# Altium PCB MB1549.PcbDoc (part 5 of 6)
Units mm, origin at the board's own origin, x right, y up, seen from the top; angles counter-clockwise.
Board outline 70 x 133.34 mm, 6 copper layers (Top Layer, Signal Layer 1, Signal Layer 2, Signal Layer 3, Signal Layer 4, Bottom Layer), stack 1.57 mm thick; 289 components, 250 nets, 1288 pads, 875 vias.
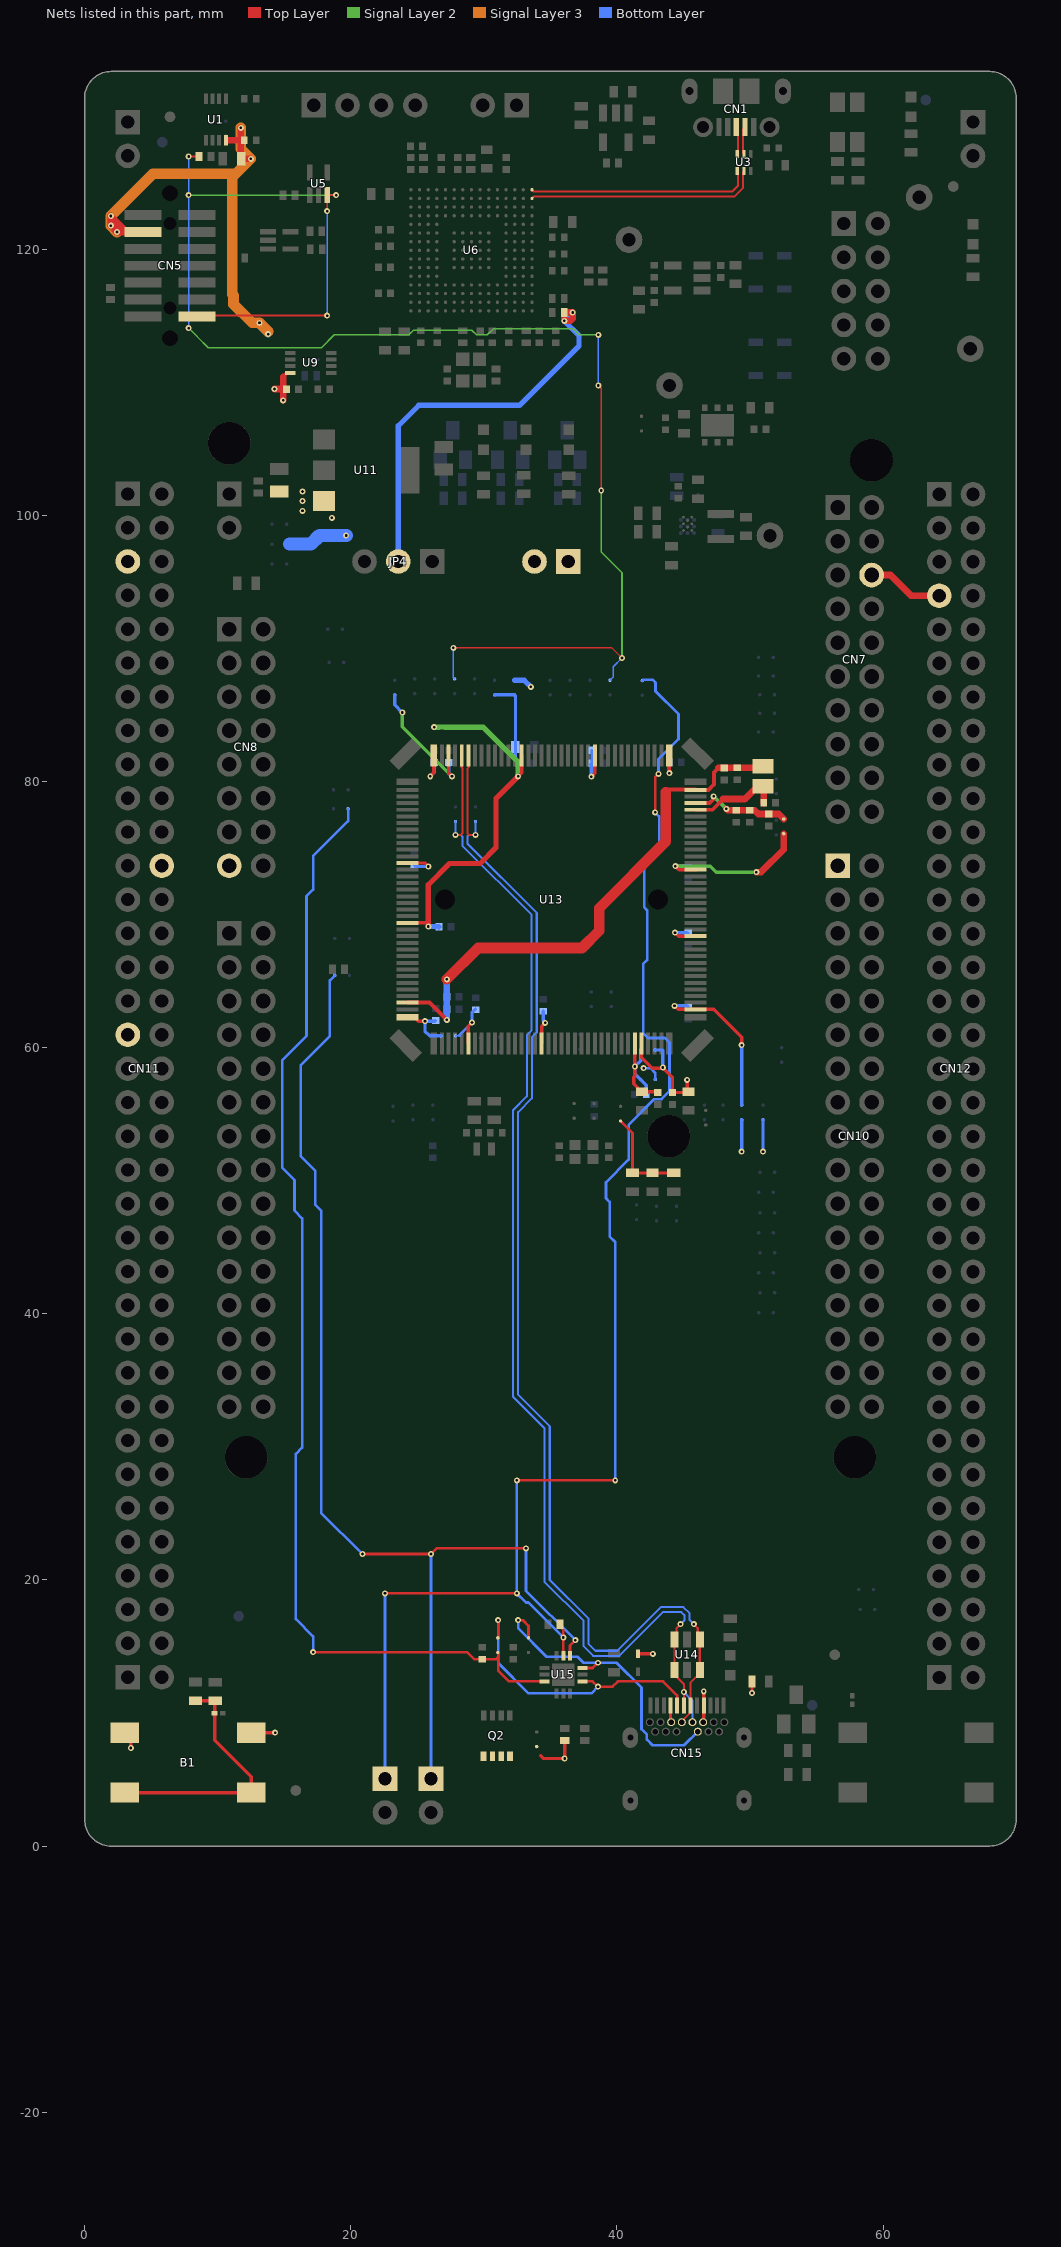
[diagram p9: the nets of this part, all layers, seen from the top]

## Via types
v1: diameter 0.45, hole 0.2, Top Layer to Bottom Layer, tented both sides, 875 vias

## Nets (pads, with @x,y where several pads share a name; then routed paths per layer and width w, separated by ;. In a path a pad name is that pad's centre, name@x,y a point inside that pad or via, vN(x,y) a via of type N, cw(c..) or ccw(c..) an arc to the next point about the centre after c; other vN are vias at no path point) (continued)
T_VCP_TX: CN5.14 R3.1 SB24.1 SB32.2 U5.3 | length 119.3
  Top Layer w0.12: v1(7.816,126.954) R3.1@8.591,126.954 ; CN5.14@8.341,114.812 CN5.14@8.458,114.929 ; CN5.14@8.453,114.934 9.516,114.934 9.587,115.005 18.22,115.005 v1(18.225,115) ; v1(18.225,122.849) U5.3@18.225,124.05 v1(18.9,124.05) ; v1(27.706,90.031) 39.62,90.031 v1(40.376,89.275) ; v1(38.6,109.75) 38.818,109.532 v1(38.818,101.857)
  Signal Layer 2 w0.12: v1(7.816,114.059) 8.475,113.4 8.475,113.395 9.28,112.59 17.796,112.59 18.765,113.559 24.365,113.559 24.71,113.904 29.097,113.904 29.442,113.559 30.261,113.559 30.716,114.014 36.714,114.014 37.169,113.559 v1(38.6,113.559) ; v1(7.816,124.05) v1(18.9,124.05) ; v1(38.818,101.857) 38.818,97.231 40.376,95.672 v1(40.376,89.275)
  Bottom Layer w0.12: v1(7.816,114.059) v1(7.816,124.05) v1(7.816,126.954) ; v1(18.225,115) v1(18.225,122.849) ; v1(27.706,90.031) 27.706,87.794 SB32.2@27.8,87.7 ; v1(38.6,109.75) v1(38.6,113.559) ; SB24.1@39.475,87.6 39.725,87.85 39.725,88.624 v1(40.376,89.275)
UCPD_CC1: C62.2 SB8.1 SB42.1 U15.3 | length 86.2
  Top Layer w0.2: v1(17.17,14.581) 28.744,14.581 29.275,14.05 C62.2@29.875,14.05 30.92,14.05 31.07,14.2 ; SB8.1@31.05,14.581 31.07,14.581 31.07,14.55 31.07,14.2 ; U15.3@34.545,12.381 31.87,12.381 31.07,13.181 31.07,14.2
  Bottom Layer w0.2: v1(17.17,14.581) 17.17,15.762 15.875,17.057 15.875,29.475 16.35,29.95 16.35,47.175 15.77,47.755 15.77,50.05 14.84,50.98 14.84,59.04 16.67,60.87 16.67,71.381 17.17,71.881 17.17,74.395 19.8,77.025 SB42.1@19.8,77.95
UCPD_CC1_C: CN15.A5 SB8.2 U15.7 | length 21.8
  Top Layer w0.2: SB8.2@31.07,15.681 v1(31.07,16.981) ; U15.7@37.395,12.381 38.17,12.381 v1(38.57,11.981) 39.67,11.981 40.07,12.381 43.47,12.381 44.52,11.331 CN15.A5@44.52,10.561
  Bottom Layer w0.2: v1(31.07,16.981) 31.07,13.781 33.37,11.481 38.07,11.481 v1(38.57,11.981)
UCPD_CC2_C: CN15.B5 SB9.2 U15.9 | length 23.4
  Top Layer w0.2: v1(32.57,16.981) 32.921,16.981 33.35,16.552 SB9.2@33.35,15.65 ; U15.9@37.395,13.381 38.17,13.381 v1(38.57,13.781)
  Bottom Layer w0.2: v1(32.57,16.981) 32.57,16.381 34.72,14.231 37.02,14.231 37.47,13.781 v1(38.57,13.781) 39.97,13.781 41.845,11.906 41.845,8.789 42.245,8.389 42.245,8.006 42.67,7.581 45.05,7.581 CN15.B5@46.07,8.601
UCPD_DBn: JP8.1 SB46.1 U15.10 | length 85.6
  Top Layer w0.2: v1(20.875,21.95) v1(26.025,21.95) 26.456,22.381 v1(33.17,22.381) ; U15.10@36.47,14.306 36.47,15.081 v1(36.87,15.481)
  Bottom Layer w0.2: SB46.1@18.8,65.425 18.427,65.052 18.427,60.863 16.25,58.686 16.25,51.825 17.325,50.75 17.325,48.2 17.775,47.75 17.775,25.05 v1(20.875,21.95) ; JP8.1@26.025,5.07 v1(26.025,21.95) ; v1(33.17,22.381) 33.17,19.181 v1(36.87,15.481)
UCPD_FLT: JP7.1 R37.1 SB45.1 U15.11 | length 114.5
  Top Layer w0.2: v1@22.6,19 v1(32.47,19) ; v1(32.47,27.481) v1(39.87,27.481) ; R37.1@35.72,16.681 35.72,16.48 35.97,16.23 v1(35.97,15.681) U15.11@35.97,14.306 ; v1(42.87,77.674) 42.87,80.32 v1(43.125,80.575)
  Bottom Layer w0.2: JP7.1@22.575,5.07 v1(22.575,19) ; v1(32.47,27.481) v1(32.47,19) 33.162,18.308 33.343,18.308 v1(35.97,15.681) ; v1(39.87,27.481) 39.87,45.401 39.454,45.817 39.454,48.397 39.17,48.681 39.17,49.881 40.875,51.586 40.875,54.2 42.8,56.125 43.35,56.125 43.95,56.725 43.95,60.37 43.595,60.725 42.325,60.725 41.97,61.08 41.97,66.281 42.27,66.581 42.27,70.32 42.037,70.553 42.037,73.948 43.17,75.081 43.17,77.374 v1(42.87,77.674) ; SB45.1@41.9,87.575 41.975,87.65 42.675,87.65 42.9,87.425 42.9,86.775 44.625,85.05 44.625,83.175 43.125,81.675 v1(43.125,80.575)
USB_DEV_HS_CN_N: CN1.2 U3.5 | length 2.1
  Top Layer w0.155: U3.5@49.541,127.154 49.482,127.213 49.482,129.024 CN1.2@49.616,129.158
USB_DEV_HS_CN_P: CN1.3 U3.6 | length 2.1
  Top Layer w0.155: CN1.3@48.966,129.158 49.1,129.024 49.1,127.213 U3.6@49.041,127.154
USB_DEV_HS_N: U3.2 U6.R14 | length 17.5
  Top Layer w0.155: U6.R14@33.616,123.804 33.751,123.938 48.814,123.938 49.416,124.54 49.472,124.596 49.472,125.785 U3.2@49.541,125.854
USB_DEV_HS_P: U3.1 U6.R15 | length 16.8
  Top Layer w0.155: U6.R15@33.616,124.454 33.751,124.32 48.657,124.32 49.091,124.754 49.091,125.804 U3.1@49.041,125.854
USB_FS_N: CN15.A7 CN15.B7 SB40.2 U13.103 U14.1 U14.6 | length 92.2
  Top Layer w0.155: U13.103@28.837,81.946 28.837,81.044 28.777,80.984 28.777,76.074 28.87,75.981 v1(29.37,75.981) ; CN15.B7@44.87,9.311 44.87,9.372 45.52,10.022 CN15.A7@45.52,10.561 45.52,12.281 46.22,12.981 U14.6@46.22,13.231 U14.1@46.22,15.531 46.07,15.681 46.07,16.381 v1(45.77,16.681)
  Bottom Layer w0.155: SB40.2@29.37,76.981 v1(29.37,75.981) 28.87,75.981 28.77,75.881 28.77,75.327 33.97,70.127 33.97,61.142 33.609,60.781 33.609,56.181 32.57,55.142 32.57,33.92 34.951,31.539 34.951,20 37.87,17.081 37.87,15.181 38.37,14.681 40.012,14.681 43.293,17.962 44.985,17.962 45.461,17.486 45.461,16.991 v1(45.77,16.681)
USB_FS_P: CN15.A6 CN15.B6 SB41.2 U13.104 U14.3 U14.4 | length 93
  Top Layer w0.155: v1(27.87,75.981) 28.27,75.981 28.396,76.108 28.396,80.984 28.337,81.044 U13.104@28.337,81.946 ; v1(44.77,16.681) 44.47,16.381 44.47,15.681 U14.3@44.32,15.531 U14.4@44.32,13.231 44.32,12.881 45.02,12.181 v1(45.02,11.581) CN15.A6@45.02,10.561
  Bottom Layer w0.155: SB41.2@27.87,76.981 v1(27.87,75.981) 28.27,75.981 28.389,75.862 28.389,75.17 33.589,69.97 33.589,61.3 33.228,60.939 33.228,56.339 32.189,55.3 32.189,33.762 34.57,31.381 34.57,19.842 37.489,16.923 37.489,15.023 38.212,14.3 40.17,14.3 43.451,17.581 44.827,17.581 45.08,17.328 45.08,16.991 v1(44.77,16.681) ; v1(45.02,11.581) 45.67,10.931 CN15.B6@45.67,9.311
USER_BUTTON: B1.3 B1.4 R38.2 R39.2 U18.1 | length 19
  Top Layer w0.25: B1.3@3.021,4.025 B1.4@12.521,4.025 12.521,5.23 9.783,7.969 9.783,9.981 9.783,10.894 R39.2@9.82,10.931 8.333,10.931 R38.2@8.33,10.934
V11_COUT: C47.2 C48.2 C78.2 C82.2 L2.1 U13.71 U13.142 | length 40.6
  Top Layer w0.3: U13.142@24.262,63.371 25.93,63.371 v1(27.22,62.081) ; 43.67,79.181 43.865,79.376 45.912,79.376 U13.71@45.912,79.371 46.86,79.371 47.275,79.786 47.275,80.686 47.62,81.031
  Top Layer w0.5: 47.62,81.031 48.05,81.031 49.05,81.031 50.87,81.031 L2.1@50.97,81.131
  Top Layer w0.8: v1(27.22,65.131) 29.57,67.481 37.37,67.481 38.67,68.781 38.67,70.481 43.67,75.481 43.67,79.181
  Bottom Layer w0.5: v1(27.22,62.081) 27.22,62.875 27.22,63.825 v1(27.22,65.131)
VBAT: C77.2 CN11.33 SB50.2 U13.6 | length 4.5
  Top Layer w0.25: U13.6@28.837,60.321 28.837,61.619 v1(29.104,61.886)
  Bottom Layer w0.127: SB50.2@27.87,60.881 28.17,60.881
  Bottom Layer w0.2: 28.17,60.881 28.17,60.952 v1(29.104,61.886)
  Bottom Layer w0.25: v1(29.104,61.886) 29.104,62.615 C77.2@29.37,62.881
VBUS_C: CN15.A4 CN15.A9 CN15.B4 CN15.B9 D1.1 Q2.5 Q2.6 Q2.7 Q2.8 R40.1 SB10.2 U16.1 | length 8.6
  Top Layer w0.25: 34.27,6.806 34.495,6.581 v1(36.07,6.581) R40.1@36.07,7.681 ; D1.1@41.57,14.456 v1(42.695,14.456) ; CN15.A4@44.02,10.561 44.02,9.361 CN15.B9@44.07,9.311 ; CN15.B4@46.47,9.311 46.52,9.361 CN15.A9@46.52,10.561 v1(46.52,11.631) ; v1(50.145,11.506) U16.1@50.145,12.381
VBUS_SENSE: C61.2 R34.2 R35.1 SB6.2 | length 7.4
  Top Layer w0.2: SB6.2@40.27,54.481 41.17,53.581 R34.2@41.17,50.581 C61.2@42.67,50.581 R35.1@44.27,50.581
VDD: B1.1 B1.2 C4.1 C36.1 CN5.3 CN11.5 JP4.2 JP5.1 R4.2 R19.2 SB17.1 U1.8 U9.8 | length 86.2
  Top Layer w0.25: B1.1@3.021,8.525 3.47,8.076 v1(3.47,7.381) ; B1.2@12.521,8.525 v1(14.316,8.525)
  Top Layer w0.3: U1.8@10.616,128.179 10.825,128.179 ; 14.916,110.416 15.204,110.704 U9.8@15.441,110.704
  Top Layer w0.5: CN5.3@4.389,121.284 CN5.3@3.161,121.284 ; 10.825,128.179 C4.1@11.741,128.179 ; v1(11.741,129.104) C4.1@11.741,128.179 ; v1(12.491,126.779) R4.2@11.766,126.779 11.741,126.804 C4.1@11.741,128.179 ; v1(14.266,109.479) C36.1@14.916,109.479 ; v1(14.916,108.629) C36.1@14.916,109.479 ; 14.916,110.416 C36.1@14.916,109.479 ; v1(2.436,121.284) 2.436,121.754 2.436,122.009 ; v1(2.436,121.284) CN5.3@3.161,121.284 ; v1(2.436,121.284) v1(1.966,121.754) v1(1.966,122.479) 2.436,122.009 ; 2.436,122.009 CN5.3@3.161,121.284 ; v1(36.041,114.604) 36.491,114.604 36.666,114.779 v1(36.666,115.229) R19.2@36.041,115.229 v1(36.041,114.604)
  Signal Layer 2 w0.5: v1(1.966,122.479) v1(1.966,121.754) v1(2.436,121.284)
  Signal Layer 3 w0.8: v1(2.436,121.284) v1(1.966,121.754) v1(1.966,122.479) 5.141,125.654 11.366,125.654 ; v1(11.741,129.104) 11.741,127.529 v1(12.491,126.779) 11.366,125.654 ; v1@13.791,113.804 v1(13.141,114.454) 12.591,114.454 11.186,115.859 11.186,116.513 11.086,116.612 11.086,125.374 11.366,125.654
  Bottom Layer w0.4: JP4.2@23.57,96.521 23.57,106.72 25.104,108.254 32.679,108.254 37.15,112.725 37.15,113.495 v1(36.041,114.604) v1(36.666,115.229)
  Bottom Layer w0.5: v1(1.966,122.479) v1(1.966,121.754) v1(2.436,121.284) ; v1(13.141,114.454) 13.141,114.254 v1(13.791,113.604)
  Bottom Layer w1: 15.425,97.832 17.007,97.832 17.65,98.475 v1(19.65,98.475)
VDD_MCU: C67.2 C69.2 C70.2 C71.2 C73.2 C74.2 C76.2 C79.2 C80.2 C81.2 JP5.2 SB2.1 SB28.1 SB50.1 SB55.1 U13.17 U13.38 U13.49 U13.59 U13.73 U13.84 U13.108 U13.121 U13.144 | length 47.7
  Top Layer w0.25: U13.144@24.262,62.271 24.797,62.271 25.087,61.981 v1(25.57,61.981) ; U13.121@24.262,73.871 25.56,73.871 v1(25.827,73.604) ; v1(25.97,80.381) 26.237,80.648 U13.108@26.237,81.946 ; U13.17@34.337,60.296 34.337,61.594 v1(34.604,61.861) ; v1(38.07,80.356) 38.337,80.623 U13.84@38.337,81.921 ; v1(43.937,80.614) U13.73@43.937,81.946 ; v1(44.322,63.138) 44.589,62.871 U13.38@45.887,62.871 ; v1(44.362,68.638) 44.629,68.371 45.912,68.371 U13.49@45.927,68.371 ; v1(44.387,73.638) 44.654,73.371 U13.59@45.912,73.371 U13.59@45.952,73.371 ; U13.38@45.912,62.871 47.28,62.871 49.37,60.781 v1(49.37,60.181)
  Top Layer w0.5: v1(50.47,73.181) 50.821,73.181 52.525,74.885 SB2.1@52.525,76.075
  Signal Layer 2 w0.25: v1(44.387,73.638) 47.013,73.638 47.47,73.181 v1(50.47,73.181)
  Bottom Layer w0.25: C73.2@24.77,73.731 24.897,73.604 v1(25.827,73.604) ; v1(25.97,80.381) 26.27,80.681 C69.2@26.27,81.431 ; C81.2@26.37,62.031 26.32,61.981 v1(25.57,61.981) 25.57,61.238 25.927,60.881 SB50.1@26.77,60.881 ; C79.2@34.47,62.731 34.47,61.995 v1(34.604,61.861) ; v1(38.07,80.356) 38.07,81.331 C71.2@38.12,81.381 38.12,82.32 C67.2@38.125,82.325 ; C70.2@43.925,81.425 43.937,81.413 v1(43.937,80.614) ; v1(44.322,63.138) 45.263,63.138 C80.2@45.37,63.031 ; v1(44.362,68.638) 45.263,68.638 45.32,68.581 C76.2@45.37,68.531 ; v1(44.387,73.638) 45.263,73.638 C74.2@45.37,73.531 ; SB55.1@49.37,55.681 v1(49.37,60.181)
  Bottom Layer w0.4: SB28.1@32.3,87.6 33.025,87.6 v1(33.525,87.1)
VDD_USB: C68.2 SB30.2 U13.106 | length 10.7
  Top Layer w0.25: U13.106@27.337,81.946 27.337,80.648 v1(27.604,80.381)
  Signal Layer 2 w0.25: v1(23.875,85.175) 23.875,84.11 v1(27.604,80.381)
  Bottom Layer w0.25: SB30.2@23.3,86.5 23.3,85.75 v1(23.875,85.175) ; C68.2@27.37,81.431 27.37,80.615 v1(27.604,80.381)
VDDA: C54.1 C56.2 CN10.1 SB3.1 SB54.2 SB55.2 U13.32 | length 14
  Top Layer w0.25: U13.32@41.837,60.296 41.837,59.278 42.666,58.448 43.398,58.448 v1(43.45,58.5) 44.17,57.78 C56.2@44.17,56.631 45.32,56.631 C54.1@45.37,56.681 45.27,56.781 v1(45.27,57.581)
  Bottom Layer w0.25: SB3.1@42.875,59.825 43.45,59.825 v1(43.45,58.5) ; v1(49.37,52.181) SB55.2@49.37,54.581 ; v1(50.97,52.181) SB54.2@50.97,54.581
VDDIO: C66.2 C72.2 C75.2 SB28.2 SB29.2 U13.95 U13.130 | length 35.7
  Top Layer w0.25: U13.130@24.262,69.371 25.827,69.371 ; v1(32.57,80.381) 32.837,80.648 U13.95@32.837,81.946
  Top Layer w0.4: v1(25.827,69.104) 25.827,69.371 25.827,72.238 27.424,73.835 29.724,73.835 30.916,75.027 30.916,78.727 v1(32.57,80.381)
  Signal Layer 2 w0.4: v1(26.27,84.081) 26.599,84.081 26.611,84.093 27.063,84.093 27.075,84.081 29.944,84.081 32.57,81.455 v1(32.57,80.381)
  Bottom Layer w0.25: SB29.2@30.8,86.5 SB28.2@32.3,86.5 32.37,86.43 C66.2@32.37,82.581 32.37,81.631 C72.2@32.62,81.381 32.57,81.331 v1(32.57,80.381)
  Bottom Layer w0.4: v1(25.827,69.104) 26.597,69.104 C75.2@26.62,69.081
VDDSMPS_CIN: C50.2 C51.2 C52.2 SB2.2 U13.69 | length 7.6
  Top Layer w0.3: U13.69@45.912,78.371 46.95,78.371 47.27,78.691 v1(47.27,78.881)
  Top Layer w0.5: v1(48.213,77.938) 48.32,77.831 C50.2@48.97,77.831 C51.2@49.97,77.831 50.343,77.831 50.624,77.55 C52.2@51.4,77.55 52.15,77.55 SB2.2@52.525,77.175
  Signal Layer 2 w0.3: v1(47.27,78.881) v1(48.213,77.938)
VIN: C43.2 CN8.15 CN11.24 U11.3
  other v1: 18.575,99.8 16.37,100.333 16.375,101.075 16.37,101.781
VLX: C49.2 L2.2 U13.68 | length 7.1
  Top Layer w0.3: U13.68@45.912,77.871 47.16,77.871 47.97,78.681
  Top Layer w0.5: 47.97,78.681 49.62,78.681 50.57,79.631 L2.2@50.97,79.631 51.02,79.581 C49.2@51.02,78.381
VREFP: C53.1 C55.2 C65.2 SB3.2 SB20.2 U13.31 | length 9
  Top Layer w0.25: U13.31@41.337,60.296 v1(41.337,58.581) 41.337,57.848 41.27,57.781 41.27,57.281 C53.1@41.87,56.681 43.02,56.681 C55.2@43.07,56.631
  Bottom Layer w0.25: SB3.2@41.775,59.825 41.775,59.019 v1(41.337,58.581) 41.337,58.038 SB20.2@41.775,57.6 42.2,57.175 C65.2@42.2,56.475
VREFP_ARD: CN7.6 CN12.7 SB20.1 | length 7.2
  Top Layer w0.5: CN7.6@59.13,95.505 60.546,95.505 62.095,93.956 CN12.7@64.21,93.956
  Bottom Layer w0.2: v1(42,58.45) 42.525,58.45 42.875,58.1 SB20.1@42.875,57.6
pads on no net: CART-1.1 CN1.4 CN5.0 CN5.1 CN5.2 CN5.9 CN11.10 CN11.26 CN11.67 CN11.70 CN12.6 CN12.16 CN12.34 CN15.A2 CN15.A3 CN15.A8 CN15.A10 CN15.A11 CN15.B2 CN15.B3 CN15.B8 CN15.B10 CN15.B11 Designator1.1 Designator2.1 Designator3.1 Designator4.1 Designator5.1 MIRE-1.1 MIRE-2.1 MIRE-3.1 U1.2 U3.4 U6.A1 U6.A2 U6.A3 U6.A4 U6.A5 U6.A6 U6.A8 U6.A9 U6.A10 U6.A11 U6.A12 U6.A13 U6.B1 U6.B2 U6.B3 U6.B4 U6.B5 U6.B6 U6.B7 U6.B8 U6.B9 U6.B10 U6.B11 U6.B12 U6.B13 U6.B14 U6.B15 U6.C2 U6.C3 U6.C4 U6.C11 U6.C12 U6.C13 U6.C14 U6.C15 U6.D1 U6.D2 U6.D3 U6.D4 U6.D10 U6.D11 U6.D13 U6.D14 U6.E1 U6.E2 U6.E3 U6.E4 U6.E12 U6.E13 U6.E14 U6.E15 U6.F1 U6.F4 U6.F14 U6.G4 U6.G14 U6.G15 U6.H1 U6.H2 U6.H3 U6.H4 U6.H14 U6.H15 U6.J2 U6.J3 U6.J4 U6.K1 U6.K2 U6.K3 U6.K12 U6.K14 U6.K15 U6.L1 U6.L3 U6.L12 U6.L13 U6.L14 U6.L15 U6.M2 U6.M3 U6.M4 U6.M5 U6.M6 U6.M7 U6.M12 U6.M13 U6.M14 U6.M15 U6.N2 U6.N4 U6.N5 U6.N6 U6.N7 U6.N11 U6.N13 U6.N14 U6.N15 U6.P2 U6.P4 U6.P5 U6.P6 U6.P7 U6.P8 U6.P9 U6.P10 U6.P11 U6.P12 U6.P13 U6.P14 U6.P15 U6.R2 U6.R3 U6.R6 U6.R7 U6.R8 U6.R9 U6.R10 U6.R11 U6.R12 U6.R13 U10.3 U10.5 U12.E1 U13.0 U14.5 U19.C1

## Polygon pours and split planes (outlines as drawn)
GND on Top Layer "GND" (solid, remove dead copper, pour order 418): -0.076,2.077 ccw(c1.924,2.077) 1.924,0.077 1.924,0.076 12.013,0.076 37.296,0.076 67.92,0.076 ccw(c67.92,2.076) 69.92,2.076 69.92,2.081 69.924,2.081 69.924,131.417 ccw(c67.924,131.417) 67.924,133.417 1.924,133.417 ccw(c1.924,131.417) -0.076,131.417 -0.076,2.077
VIN on Top Layer "V_IN" (solid, pour order 324): 13.698,102.781 15.67,102.781 16.07,102.381 19.27,102.381 19.67,101.981 19.67,99.881 19.27,99.481 13.87,99.481 13.27,100.081 13.27,102.381
NetC39_2 on Top Layer "NO_TH" (solid, pour order 330): 47.033,105.008 47.033,106.169 46.253,106.949 41.5,106.949 41.27,106.719 41.27,105.48 42.025,104.725 46.75,104.725
5V on Top Layer "NO_TH" (solid, remove dead copper, pour order 404): 58.547,113.496 58.547,110.997 58.05,110.5 49.6,110.5 48.075,108.975 48.075,104.95 48.45,104.575 49.675,104.575 50.7,105.6 50.7,108.65 50.95,108.9 66.375,108.9 67.666,110.175 67.666,118.154 67.366,118.454 64.866,118.454 64.116,119.204 64.116,123.929 63.516,124.529 59.188,124.529 58.525,123.865 58.525,113.518
1V8 on Top Layer "NO_TH" (solid, pour order 416): 50.26,98.896 50.26,97.235 50.075,97.05 46.975,97.05 45.75,98.275 45.75,98.55 46.325,99.125 50.031,99.125
VDD_MCU on Signal Layer 3 "VDD_MCU" (solid, pour order 378): 44.47,89.524 ccw(c43.519,89.524) 43.519,90.475 35.9,90.475 cw(c35.9,91.145) 35.23,91.145 35.23,97.445 ccw(c34.45,97.445) 34.45,98.225 33.225,98.225 ccw(c33.225,97.3) 32.3,97.3 32.3,91.55 32.3,88.9 cw(c31.3,88.9) 31.3,87.9 23.508,87.9 ccw(c23.508,86.962) 22.57,86.962 22.57,62.28 ccw(c23.403,62.28) 23.403,61.447 25.613,61.447 ccw(c25.527,61.881) 25.97,61.881 25.97,65.503 cw(c26.767,65.503) 26.767,66.3 33.575,66.3 cw(c33.575,65.905) 33.97,65.905 33.97,61.775 ccw(c34.395,61.775) 34.395,61.35 36.12,61.35 ccw(c36.12,61.9) 36.67,61.9 36.67,62.256 cw(c37.131,62.264) 37.123,62.724 44.77,62.724 ccw(c44.792,63.503) 45.57,63.481 45.57,75.298 ccw(c45.187,75.298) 45.187,75.681 45.07,75.681 cw(c45.07,76.281) 44.47,76.281
5V_UCPD on Signal Layer 3 "5V_USB_TYPEC" (solid, pour order 382): 36.97,60.85 35.475,59.355 35.475,57.364 36.97,55.869 36.97,55.431 36.97,13.581 cw(c36.17,13.581) 36.17,12.781 30.77,12.781 ccw(c30.77,11.881) 29.87,11.881 29.87,10.481 ccw(c30.77,10.481) 30.77,9.581 40.27,9.581 ccw(c40.27,10.531) 41.22,10.531 41.22,19.731 41.17,19.781 41.17,20.628 41.17,50.381 41.17,50.633 ccw(c40.87,50.633) 40.87,50.933 cw(c40.87,51.233) 40.57,51.233 40.57,59.081 40.57,60.081 cw(c40.839,60.081) 40.839,60.35 41.337,60.35 47.17,60.35 ccw(c47.154,61.065) 47.87,61.081 47.87,92.3 47.9,97.025 cw(c48.475,97.025) 48.475,97.6 ccw(c48.475,97.95) 48.825,97.95 48.825,112.825 ccw(c48.325,112.825) 48.325,113.325 47.05,113.325 ccw(c47.05,112.5) 46.225,112.5 46.225,100.325 cw(c45.35,100.325) 45.35,99.45 ccw(c45.35,98.77) 44.67,98.77 44.67,76.381 ccw(c45.07,76.381) 45.07,75.981 45.46,75.981 cw(c45.46,75.471) 45.97,75.471 45.97,63.264 cw(c45.207,63.284) 45.187,62.521 37.41,62.521 ccw(c37.411,62.081) 36.97,62.08
AGND on Signal Layer 3 "AGND" (solid, remove dead copper, pour order 362): 59.403,72.474 69.068,72.474 cw(c69.073,71.8) 69.747,71.804 69.747,2.008 cw(c67.944,2.008) 67.944,0.204 53.47,0.204 53.07,0.181 cw(c53.07,0.781) 52.47,0.781 52.47,13.681 ccw(c52.42,13.731) 52.47,13.781 52.47,16.281 ccw(c51.67,16.281) 51.67,17.081 49.97,17.081 42.77,17.081 cw(c42.77,18.298) 41.553,18.298 41.553,50.801 cw(c42.084,50.801) 42.084,51.332 53.47,51.332 ccw(c53.495,51.706) 53.87,51.681 53.87,72.081 cw(c54.263,72.081) 54.263,72.474 57.87,72.474
VREFP_ARD on Signal Layer 3 "VREFP" (solid, remove dead copper, pour order 356): 61.4,76.475 cw(c60.9,76.475) 60.9,75.975 51.807,75.975 ccw(c51.807,75.138) 50.97,75.138 50.97,59.281 cw(c50.07,59.281) 50.07,58.381 49.17,58.381 44.87,58.381 ccw(c44.87,57.981) 44.47,57.981 44.47,57.781 cw(c44.262,57.781) 44.262,57.573 41.17,57.573 cw(c41.17,57.873) 40.87,57.873 40.87,59.681 cw(c41.183,59.694) 41.17,60.007 47.17,60.007 47.296,60.007 ccw(c47.296,60.881) 48.17,60.881 48.17,89.7 48.17,96.395 cw(c49.125,96.395) 49.125,97.35 61,97.35 cw(c61,96.95) 61.4,96.95
VDDA on Signal Layer 3 "AVDD" (solid, remove dead copper, pour order 360): 51.27,73.981 51.27,74.881 cw(c51.87,74.881) 51.87,75.481 59.707,75.481 cw(c59.707,74.919) 60.27,74.919 60.27,73.081 cw(c59.852,73.063) 59.87,72.645 54.134,72.645 ccw(c54.134,72.081) 53.57,72.081 53.57,52.481 cw(c52.82,52.431) 52.87,51.681 45.27,51.681 cw(c45.27,52.281) 44.67,52.281 44.67,57.786 cw(c45.07,57.786) 45.07,58.186 50.67,58.186 ccw(c50.672,58.783) 51.27,58.781
GND on Signal Layer 3 "GND" (solid, pour order 384): 28.77,55.881 cw(c28.77,55.681) 28.97,55.681 ccw(c29.77,55.681) 29.77,54.881 32.47,54.881 cw(c32.47,54.181) 33.17,54.181 33.17,15.881 cw(c32.67,15.881) 32.67,15.381 13.77,15.381 ccw(c13.77,14.381) 12.77,14.381 12.77,10.481 cw(c12.17,10.481) 12.17,9.881 2.97,9.881 ccw(c2.97,8.981) 2.07,8.981 2.07,7.681 ccw(c2.97,7.681) 2.97,6.781 14.57,6.781 ccw(c14.57,7.581) 15.37,7.581 15.37,12.181 cw(c16.07,12.181) 16.07,12.881 29.27,12.881 cw(c29.27,12.581) 29.57,12.581 29.57,0.881 cw(c29.07,0.881) 29.07,0.381 1.97,0.381 cw(c1.97,2.081) 0.27,2.081 0.27,55.481 cw(c0.67,55.481) 0.67,55.881
VDD on Signal Layer 3 "VDD" (solid, pour order 410): 37.85,99.075 ccw(c37.325,99.075) 37.325,99.6 34.8,99.6 cw(c34.8,99.975) 34.425,99.975 ccw(c33.85,99.975) 33.85,100.55 30.75,100.55 ccw(c30.75,100.25) 30.45,100.25 30.45,91.35 cw(c30.05,91.35) 30.05,90.95 22.95,90.95 cw(c22.95,91.4) 22.5,91.4 22.5,92.25 cw(c22.85,92.25) 22.85,92.6 24.425,92.6 ccw(c24.425,93.075) 24.9,93.075 24.9,99.925 ccw(c24.525,99.925) 24.525,100.3 19.5,100.3 ccw(c19.5,99.975) 19.175,99.975 19.175,60 ccw(c19.575,60) 19.575,59.6 27.475,59.6 ccw(c27.475,60.1) 27.975,60.1 27.975,62.075 cw(c28.675,62.075) 28.675,62.775 29,62.775 cw(c29,62.225) 29.55,62.225 29.55,55.85 ccw(c29.975,55.85) 29.975,55.425 32.775,55.425 cw(c32.775,54.7) 33.5,54.7 33.5,15.58 cw(c33.07,15.58) 33.07,15.15 13.775,15.15 ccw(c13.775,14.4) 13.025,14.4 13.025,10.325 cw(c12.35,10.325) 12.35,9.65 2.925,9.65 ccw(c2.925,9.175) 2.45,9.175 2.45,7.5 ccw(c2.95,7.5) 2.95,7 14.125,7 ccw(c14.125,7.8) 14.925,7.8 14.925,12.3 cw(c15.9,12.3) 15.9,13.275 35.744,13.275 ccw(c35.744,13.756) 36.225,13.756 36.225,59.9 ccw(c35.325,59.9) 35.325,60.8 34.239,60.8 cw(c34.239,61.45) 33.589,61.45 33.589,65.386 ccw(c32.975,65.386) 32.975,66 26.793,66 ccw(c26.793,65.525) 26.318,65.525 26.318,61.743 cw(c25.8,61.743) 25.8,61.225 22.8,61.225 cw(c22.8,61.7) 22.325,61.7 22.325,87.4 cw(c23.125,87.4) 23.125,88.2 31.2,88.2 ccw(c31.2,88.9) 31.9,88.9 31.9,97.3 cw(c33.05,97.3) 33.05,98.45 34.825,98.45 cw(c34.825,97.775) 35.5,97.775 35.5,95.6 ccw(c36.075,95.6) 36.075,95.025 37.425,95.025 ccw(c37.425,95.45) 37.85,95.45
VBAT on Signal Layer 3 "VBAT" (solid, remove dead copper, pour order 348): 28.853,62.55 ccw(c28.853,62.002) 28.305,62.002 28.305,60.055 cw(c27.5,60.055) 27.5,59.25 18.95,59.25 cw(c18.95,59.9) 18.3,59.9 18.3,65.925 ccw(c17.575,65.925) 17.575,66.651 0.506,66.651 ccw(c0.506,66.271) 0.126,66.271 0.126,56.542 ccw(c0.532,56.542) 0.532,56.135 28.546,56.135 ccw(c28.546,56.846) 29.257,56.846 29.257,62.146 ccw(c28.853,62.147)
3V3 on Signal Layer 3 "3V3" (solid, remove dead copper, pour order 344): 41.375,99.75 41.125,99.75 ccw(c41.125,98.85) 40.225,98.85 40.225,91.2 cw(c39.775,91.2) 39.775,90.75 38.625,90.75 cw(c38.625,91.4) 37.975,91.4 37.975,99.2 ccw(c37.437,99.213) 37.45,99.75 34.8,99.75 cw(c34.8,99.975) 34.575,99.975 34.575,100.112 ccw(c33.95,100.112) 33.95,100.737 33.575,100.738 30.725,100.738 ccw(c30.725,100.238) 30.225,100.238 30.225,91.475 cw(c29.85,91.475) 29.85,91.1 23.05,91.1 cw(c23.05,91.45) 22.7,91.45 22.7,91.9 cw(c23.2,91.9) 23.2,92.4 24.375,92.4 ccw(c24.375,93.225) 25.2,93.225 25.2,100.375 ccw(c24.844,100.381) 24.85,100.738 19.77,100.738 cw(c19.792,101.159) 19.37,101.181 19.37,101.981 ccw(c18.97,101.981) 18.97,102.381 15.77,102.381 ccw(c15.77,101.672) 15.061,101.672 15.061,83.125 cw(c14.538,83.125) 14.538,82.602 5.18,82.602 cw(c5.18,83.495) 4.287,83.495 4.287,94.362 cw(c5.163,94.35) 5.175,95.226 8,95.226 ccw(c8,95.937) 8.711,95.937 8.711,101.572 cw(c9.36,101.572) 9.36,102.222 13.429,102.222 ccw(c13.429,102.692) 13.899,102.692 13.899,102.718 13.899,104.81 cw(c14.17,104.81) 14.17,105.081 17.97,105.081 cw(c17.97,104.781) 18.27,104.781 18.27,103.83 ccw(c18.67,103.83) 18.67,103.43 33.15,103.43 41.18,103.43 ccw(c41.18,104.35) 42.1,104.35 42.1,110.3 cw(c42.925,110.3) 42.925,111.125 45.175,111.125 cw(c45.175,110.475) 45.825,110.475 45.825,100.6 cw(c44.975,100.6) 44.975,99.75
VIN on Signal Layer 3 "VIN" (solid, remove dead copper, pour order 358): 18.87,101.581 ccw(c18.37,101.581) 18.37,102.081 15.97,102.081 ccw(c15.97,101.381) 15.27,101.381 15.27,99.181 15.305,90.081 15.305,78.546 cw(c14.84,78.546) 14.84,78.081 4.77,78.081 ccw(c4.77,77.481) 4.17,77.481 4.17,71.963 ccw(c4.762,71.963) 4.762,71.371 18.37,71.371 ccw(c18.365,71.876) 18.87,71.881
5V_USB_STLK on Signal Layer 3 "5V_STLK" (solid, remove dead copper, pour order 364): 62.1,92.281 cw(c62.1,92.756) 61.625,92.756 61.625,116.15 cw(c62.453,116.153) 62.45,116.981 69.646,116.984 69.646,92.957 cw(c68.97,92.957) 68.97,92.281
VBUS_C on Signal Layer 3 "VBUSc" (solid, remove dead copper, pour order 388): 42.27,16.681 51.07,16.681 cw(c51.07,15.581) 52.17,15.581 52.17,0.681 cw(c51.67,0.681) 51.67,0.181 30.37,0.181 cw(c30.37,0.681) 29.87,0.681 29.87,8.681 cw(c30.27,8.681) 30.27,9.081 40.67,9.081 ccw(c40.67,10.081) 41.67,10.081 41.67,16.081 cw(c42.27,16.081)
3V3_STLK on Signal Layer 3 "3V3_STLK_L04_P390" (solid, remove dead copper, pour order 390): 15.8,109.204 16.904,108.1 19.25,108.1 20.325,109.204 43.766,109.204 44.966,110.404 44.966,116.254 34.716,126.504 34.716,128.529 34.691,128.554 34.691,131.354 33.866,132.179 15.291,132.179 14.541,131.429 14.541,110.429 15.766,109.204
5V_USB_CHGR on Signal Layer 3 "5V_USB_CHGR_L04_P392" (solid, remove dead copper, pour order 392): 58.3,110.7 57.8,110.2 52.37,110.2 35.641,126.929 35.641,129.779 36.741,130.879 62.641,130.879 63.716,129.804 63.716,124.829 63.016,124.129 59.229,124.129 58.3,123.2
GND on Signal Layer 3 "GND_L04_P394" (solid, remove dead copper, pour order 394): 8.75,127.975 8.75,127.575 8.425,127.25 5.5,127.25 0.775,122.525 0.075,122.525 0.1,122.55 0.116,127.975 0.116,131.829 1.466,133.179 8.75,133.179
VDD on Signal Layer 3 "VDD_L04_P396" (solid, remove dead copper, pour order 396): 15.212,108.363 15.212,109.038 15.15,109.1 14.1,110.15 14.1,131.7 13.5,132.3 9.8,132.3 9.125,131.625 9.125,127.225 8.675,126.775 5.75,126.775 1.55,122.575 1.55,116.7 2.95,115.3 4.975,115.3 6.05,114.225 6.05,111 6.65,110.4 9.9,110.4 12.275,108.025 14.875,108.025
5V on Signal Layer 3 "5V" (solid, pour order 406): 14.875,81.865 ccw(c14.315,81.865) 14.315,82.425 4.646,82.425 cw(c4.646,83.025) 4.046,83.025 4.046,114.379 ccw(c3.5,114.379) 3.5,114.925 0.9,114.925 ccw(c0.9,114.475) 0.45,114.475 0.45,79.075 ccw(c1.05,79.075) 1.05,78.475 14.675,78.475 ccw(c14.675,78.675) 14.875,78.675
GND on Signal Layer 2 "GND" (solid, pour order 414): -0.2,134.65 68.685,134.65 cw(c68.685,132.11) 71.225,132.11 71.225,0.9 cw(c69.325,0.9) 69.325,-1 0.39,-1 cw(c0.39,1.54) -2.15,1.54 -2.15,132.7 cw(c-0.2,132.7)
5V on Signal Layer 2 "5V_L03_P402" (solid, remove dead copper, pour order 402): 58.591,115.503 58.591,110.609 59.225,109.975 62.9,109.975 63.616,110.691 63.616,124.429 61.641,126.404 50.866,126.404 48.191,123.729 41.841,123.729 36.066,117.954 26.266,117.954 23.766,120.454 4.541,120.454 1.091,117.004 1.091,113.079 1.691,112.479 3.941,112.479 5.466,114.004 38.241,114.004 44.791,120.554 57.771,120.554 58.63,119.695
VDD on Signal Layer 2 "VDD" (solid, pour order 412): 22.175,107.675 ccw(c21.6,107.675) 21.6,108.25 5.45,108.25 ccw(c5.45,107.425) 4.625,107.425 4.625,95.875 cw(c4.025,95.875) 4.025,95.275 1.025,95.275 cw(c1.025,95.75) 0.55,95.75 0.55,110.075 cw(c1.225,110.075) 1.225,110.75 26.877,110.75 cw(c26.872,109.897) 27.725,109.893 27.725,95.45 cw(c27.225,95.45) 27.225,94.95 22.7,94.95 cw(c22.7,95.475) 22.175,95.475
GND on Bottom Layer "GND" (solid, remove dead copper, pour order 342): 0.101,2.001 ccw(c2.101,2.001) 2.101,0.001 2.101,0 12.191,0 37.474,0 68.097,0 ccw(c68.097,2) 70.097,2 70.097,2.005 70.101,2.005 70.101,131.341 ccw(c68.101,131.341) 68.101,133.341 2.101,133.341 ccw(c2.101,131.341) 0.101,131.341 0.101,2.001
GND on Signal Layer 1 "GND" (solid, remove dead copper, pour order 370): 0,2.001 ccw(c2,2.001) 2,0.001 2,0 12.089,0 37.373,0 67.996,0 ccw(c67.996,2) 69.996,2 69.996,2.005 70,2.005 70,131.341 ccw(c68,131.341) 68,133.341 2,133.341 ccw(c2,131.341) 0,131.341 0,2.001
GND on Signal Layer 4 "VDD" (solid, remove dead copper, pour order 376): 0,2.001 ccw(c2,2.001) 2,0.001 2,0 12.089,0 37.373,0 67.996,0 ccw(c67.996,2) 69.996,2 69.996,2.005 70,2.005 70,131.341 ccw(c68,131.341) 68,133.341 2,133.341 ccw(c2,131.341) 0,131.341 0,2.001

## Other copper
Top Layer:
  region net 5V_UCPD: 30.47,9.311 32.64,9.311 33.97,7.981 34.47,8.481 34.47,9.981 35.57,11.081 35.57,11.731 34.126,11.731 33.076,10.681 30.82,10.681 30.47,10.331
  region net VBUS_C: 29.745,8.781 32.92,8.781 33.97,7.731 34.47,8.231 34.47,6.781 33.92,6.231 29.403,6.231 29.02,6.614 29.02,8.456 29.345,8.781
  text "1" at 51.429,1.313 h2
Signal Layer 1:
  text "2" at 52.679,1.313 h2
Signal Layer 2:
  text "3" at 54.179,1.313 h2
Signal Layer 3:
  text "4" at 56.429,1.313 h2
Signal Layer 4:
  text "5" at 57.929,1.313 h2
Bottom Layer:
  text "6" at 59.429,1.313 h2
Multi-Layer:
  pour cut-out: 51.136,2.91 51.136,0.91 59.636,0.91 59.636,2.91

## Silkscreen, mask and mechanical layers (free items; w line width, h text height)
Top Overlay:
  lines w0.1: 31.175,112.425 32.225,111.375 32.225,110.3 ; 31.9,110.3 34.625,110.3
  lines w0.127: 1.98,14.022 1.98,11.46 7.06,11.46 7.06,14.022 ; 1.98,100.89 1.98,102.871 ; 7.06,100.89 7.06,102.871 ; 7.77,39.281 9.07,39.281 ; 7.77,54.381 9.07,54.381 ; 7.87,34.481 9.17,34.481 ; 7.87,42.281 9.17,42.281 ; 7.87,49.881 9.17,49.881 ; 14.97,92.381 16.97,92.381 17.837,92.381 17.837,87.081 ; 15.07,57.281 17.66,57.281 17.66,61.381 ; 15.07,69.581 17.66,69.581 17.66,65.481 ; 15.17,54.181 18.57,54.181 18.57,51.681 ; 15.17,76.781 16.47,76.781 ; 15.17,77.681 16.47,77.681 17.87,77.681 17.87,81.681 ; 15.27,34.781 18.67,34.781 18.67,37.281 ; 15.27,44.181 18.67,44.181 18.67,41.181 ; 15.27,44.981 18.67,44.981 18.67,47.481 ; 15.87,72.871 17.57,72.871 17.57,73.971 ; 15.87,76.781 17.57,76.781 17.57,75.681 ; 51.57,49.281 51.57,42.381 53.67,42.381 54.97,42.381 ; 51.57,52.481 51.57,59.681 53.67,59.681 54.97,59.681 ; 51.57,90.781 53.17,93.381 ; 51.77,42.381 55.17,42.381 ; 51.77,84.381 52.47,81.881 ; 51.87,62.081 51.87,60.081 51.97,60.081 54.77,60.081 ; 51.87,64.981 51.87,66.981 51.97,66.981 54.77,66.981 ; 51.97,82.181 52.47,81.881 ; 52.57,93.181 53.17,93.381 ; 52.67,82.481 52.47,81.881 ; 53.27,92.781 53.17,93.381 ; 53.87,33.581 53.87,33.281 53.87,32.781 55.17,32.781 ; 53.87,37.581 53.87,37.881 53.87,38.381 55.17,38.381 ; 60.57,32.781 61.87,32.781 61.87,33.281 61.87,33.581 ; 60.57,53.681 61.87,53.681 61.87,53.181 61.87,52.881 ; 68.02,100.865 68.02,102.846 ; 62.94,11.406 62.94,13.997 68.02,13.997 68.02,11.406 62.94,11.406 ; 62.94,11.406 62.94,11.406 ; 15.17,72.871 16.47,72.871 15.17,72.871 ; 39.245,122.331 39.245,124.631 40.045,124.631 42.445,124.631 42.445,122.331 39.245,122.331 ; 45.37,110.631 48.37,110.631 48.37,112.531 45.57,112.531 45.37,112.531 45.37,110.631 ; 50.495,92.931 50.495,93.131 50.495,95.931 52.395,95.931 52.395,92.931 50.495,92.931 ; 61.245,119.356 64.445,119.356 64.445,121.656 62.045,121.656 61.245,121.656 61.245,119.356 ; 65.395,109.031 65.395,110.931 65.595,110.931 67.775,110.931 67.775,109.031 65.395,109.031
  text "STLK" at 44.475,129.1 h1.5 r90
  text "RES" at 16.175,128.075 h1.5
  text "STLK / NRST" at 32.3,127.15 h1.5
  text "GND" at 69.075,126.95 h1.02 r90
  text "GND" at 1.693,126.764 h1.02 r90
  text "COM" at 59.075,125.325 h1.02
  text "3V3 / STLK" at 39.445,122.531 h1.27
  text "5V_STLK" at 50.675,120.9 h1.27
  text "5V / STLK" at 61.545,119.556 h1.27
  text "5V_VIN" at 51.625,118.35 h1.27
  text "5V_EXT" at 51.3,115.825 h1.27
  text "5V_USB_C" at 49.65,112.775 h1.27
  text "3V3" at 45.67,111.031 h1.02
  text "5V_CHGR" at 50.225,110.7 h1.27
  text "5V" at 65.695,109.431 h1.02
  text "E" at 35.15,109.15 h12
  text "5V" at 60.25,108 h1.06 r90
  text "MCLK" at 52.17,100.481 h1.27
  text "D15 / SCL" at 61.57,99.681 h1.27 r45
  text "VDD_MCU" at 20.47,98.481 h1.02
  text "IDD" at 34.17,98.381 h1.2
  text "T_NRST" at 8.9,98.075 h1.27 r90
  text "SD" at 53.67,97.681 h1.27
  text "D14 / SDA" at 61.47,96.981 h1.27 r45
  text "SCK" at 52.97,95.081 h1.27
  text "VREFP" at 60.67,94.481 h1.27 r45
  text "3V3" at 25.17,93.881 h1.02
  text "1V8" at 19.07,93.681 h1.02
  text "1V8" at 51.995,93.231 h1.02 r90
  text "FS" at 53.67,92.581 h1.27
  text "GND" at 60.97,92.581 h1.27 r45
  text "D0" at 15.07,90.981 h1.27
  text "NC" at 8.17,90.681 h1.27 r45
  text "D13 / SCK" at 61.37,90.081 h1.27 r45
  text "D1" at 14.97,88.581 h1.27
  text "IOREF" at 7.67,87.781 h1.27 r45
  text "SAI_C" at 51.47,87.381 h1.27 r90
  text "D12 / MISO" at 61.27,87.381 h1.27 r45
  text "D2" at 15.07,85.981 h1.27
  text "NRST" at 7.67,85.181 h1.27 r45
  text "MOSI" at 52.47,84.881 h1.27
  text "D3" at 15.07,83.481 h1.27
  text "SPI_B" at 51.47,83.481 h1.27 r90
  text "D11 / MOSI" at 59.97,83.381 h1.27 r45
  text "3V3" at 7.87,82.881 h1.27 r45
  text "SCK" at 52.97,82.381 h1.27
  text "D10 / CS/PWM" at 60.37,80.981 h1.27 r45
  text "CK" at 15.07,80.881 h1.27
  text "5V" at 8.07,80.581 h1.27 r45
  text "NSS" at 52.97,79.881 h1.27
  text "D9 / PWM" at 61.07,78.681 h1.27 r45
  text "CMD" at 15.07,78.381 h1.27
  text "SDMMC" at 18.27,78.381 h1.27 r90
  text "MISO" at 52.47,78.081 h1.27
  text "GND" at 7.77,77.881 h1.27 r45
  text "D8" at 61.17,77.081 h1.27 r45
  text "PF3" at 14.87,75.681 h1.27
  text "GND" at 7.77,74.981 h1.27 r45
  text "IO" at 17.97,74.381 h1.27 r90
  text "PF5" at 14.916,73.625 h1.27
  text "D7" at 61.27,72.981 h1.27 r45
  text "VIN" at 7.97,72.681 h1.27 r45
  text "AVDD" at 53.07,72.481 h1.27 r45
  text "AGND" at 52.97,69.781 h1.27 r45
  text "D6 / PWM" at 61.17,69.681 h1.27 r45
  text "SCK" at 14.97,68.081 h1.27
  text "A0" at 8.17,67.881 h1.27 r45
  text "GND" at 53.47,67.481 h1.27 r45
  text "D5 / PWM" at 61.17,66.981 h1.27 r45
  text "RX" at 15.07,65.781 h1.27
  text "A6" at 53.37,65.481 h1.27
  text "A1" at 8.37,65.381 h1.27 r45
  text "D4" at 61.27,65.381 h1.27 r45
  text "A7" at 53.47,63.081 h1.27
  text "TX" at 15.039,62.971 h1.27
  text "A2" at 8.37,62.681 h1.27 r45
  text "ADC" at 52.27,62.281 h1.27 r90
  text "D3 / PWM" at 61.17,61.781 h1.27 r45
  text "USART" at 18.07,61.581 h1.27 r90
  text "RTS" at 14.97,60.581 h1.27
  text "A8" at 53.47,60.581 h1.27
  text "A3" at 8.37,60.181 h1.27 r45
  text "D2" at 61.37,59.981 h1.27 r45
  text "CS" at 53.47,58.081 h1.27
  text "CTS" at 14.87,57.981 h1.27
  text "A4" at 8.27,57.581 h1.27 r45
  text "D1 / TX" at 61.77,56.881 h1.27 r45
  text "CLK" at 53.07,55.606 h1.27
  text "A5" at 8.37,55.181 h1.27 r45
  text "GND" at 15.47,54.881 h1.27 r45
  text "D0 / RX" at 61.77,54.381 h1.27 r45
  text "1" at 9.37,53.081 h1.27 r90
  text "MCLK" at 15,52.881 h1.27
  text "GND" at 52.57,52.881 h1.27
  text "2" at 9.47,50.581 h1.27 r90
  text "IO3" at 52.97,50.481 h1.27
  text "COMP" at 8.27,50.381 h1.27 r90
  text "FS" at 15.07,50.381 h1.27
  text "QSPI" at 51.97,49.581 h1.27 r90
  text "SCK" at 14.97,47.881 h1.27
  text "F" at 19.97,47.881 h12
  text "IO1" at 53.07,47.881 h1.27
  text "SAI_A" at 19.07,46.281 h1.27 r90
  text "SD" at 15.07,45.381 h1.27
  text "IO0" at 52.97,45.381 h1.27
  text "SCL" at 9.37,45.281 h1.27 r90
  text "I2C_B" at 8.17,44.281 h1.27 r90
  text "SD" at 15.17,42.781 h1.27
  text "IO2" at 53.07,42.781 h1.27
  text "SDA" at 9.37,42.481 h1.27 r90
  text "TIMER" at 61.57,41.881 h1.27 r90
  text "L" at 19.77,40.481 h12
  text "SCK" at 14.97,40.281 h1.27
  text "J" at 27.806,39.881 h18
  text "GND" at 7.87,39.481 h1.27 r45
  text "GND" at 53.57,39.381 h1.27 r45
  text "G" at 40.37,39.081 h10
  text "MCLK" at 14.77,37.781 h1.27
  text "MB1549C" at 27.125,37.6 h2
  text "RX" at 9.44,37.381 h1.27 r90
  text "SAI_B" at 19.27,35.781 h1.27 r90
  text "CAN" at 8.27,35.681 h1.27 r90
  text "FS" at 15.27,35.281 h1.27
  text "TX" at 9.44,34.881 h1.27 r90
  text "TIMER" at 54.97,33.881 h1.27 r90
  text "IO" at 8.37,32.381 h1.27 r45
  text "IO" at 15.67,32.381 h1.27 r45
  text "C" at 39.77,29.881 h12
  text "I" at 20.77,29.581 h12
  text "H" at 28.37,28.881 h15
  text "USB_5V" at 51.075,15.775 h1.02
  text "GND" at 3.37,10.181 h1.27
  text "GND" at 64.27,10.181 h1.27
  text "USER" at 5.97,1.281 h1.02
  text "RESET" at 60.27,1.181 h1.02
  text "USB" at 37.4,0.975 h1.02
Bottom Overlay:
  text "PC9" at 62.57,100.881 h1.27 r315
  text "PC8" at 69.17,100.781 h1.27 r315
  text "PC11" at 8.47,100.381 h1.27 r315
  text "PC10" at 1.97,99.681 h1.27 r315
  text "PB8" at 62.57,98.381 h1.27 r315
  text "PD2" at 8.27,98.181 h1.27 r315
  text "PC6" at 69.07,98.181 h1.27 r315
  text "PC12" at 2.07,97.581 h1.27 r315
  text "NC" at 68.77,96.081 h1.27 r315
  text "PB9" at 62.57,95.881 h1.27 r315
  text "VDD" at 1.67,95.481 h1.27 r315
  text "5V / EXT" at 8.17,95.281 h1.27 r315
  text "5V / STLK" at 69.27,92.981 h1.27 r315
  text "GND" at 8.47,92.881 h1.27 r315
  text "VREFP" at 62.77,92.781 h1.27 r315
  text "PH3" at 1.87,92.581 h1 r315
  text "BOOT0" at 1.97,91.481 h1 r315
  text "NC" at 7.87,90.781 h1.27 r315
  text "PF6" at 1.57,90.581 h1.27 r315
  text "PD8" at 69.07,90.481 h1.27 r315
  text "GND" at 62.77,90.381 h1.27 r315
  text "PF7" at 1.57,88.181 h1.27 r315
  text "PA12" at 69.17,87.981 h1.27 r315
  text "PA5" at 62.67,87.781 h1.27 r315
  text "IOREF" at 8.77,87.281 h1.27 r315
  text "PA11" at 69.17,85.481 h1.27 r315
  text "PA6" at 62.67,85.281 h1.27 r315
  text "NRST" at 8.57,85.081 h1.27 r315
  text "PA13" at 1.97,84.981 h1.27 r315
  text "NC" at 68.87,83.081 h1.27 r315
  text "3V3" at 8.17,82.981 h1.27 r315
  text "PA7" at 62.57,82.781 h1.27 r315
  text "PA14" at 1.97,82.481 h1.27 r315
  text "5V" at 8.07,80.481 h1.27 r315
  text "PB11" at 69.27,80.381 h1.27 r315
  text "PB6" at 62.57,80.281 h1.27 r315
  text "PA15" at 1.97,79.881 h1.27 r315
  text "PC7" at 62.67,77.781 h1.27 r315
  text "GND" at 69.17,77.681 h1.27 r315
  text "GND" at 1.77,77.581 h1.27 r315
  text "GND" at 8.67,77.581 h1.27 r315
  text "GND" at 8.67,75.381 h1.27 r315
  text "PB7" at 1.67,75.281 h1.27 r315
  text "PA9" at 62.57,75.281 h1.27 r315
  text "PB2" at 69.07,75.281 h1.27 r315
  text "PA8" at 62.57,72.781 h1.27 r315
  text "VIN" at 8.57,72.581 h1.27 r315
  text "PB1" at 69.17,72.481 h1.27 r315
  text "PC13" at 2.07,72.181 h1.27 r315
  text "NC" at 8.37,70.481 h1.27 r315
  text "PB15" at 69.17,70.181 h1.27 r315
  text "PB10" at 62.67,69.881 h1.27 r315
  text "PC14" at 1.97,69.781 h1.27 r315
  text "PB14" at 69.07,67.781 h1.27 r315
  text "PB4" at 62.67,67.581 h1.27 r315
  text "PA0" at 8.57,67.281 h1.27 r315
  text "PC15" at 1.97,67.181 h1.27 r315
  text "PB13" at 69.17,65.181 h1.27 r315
  text "PH0" at 1.67,65.081 h1.27 r315
  text "PB5" at 62.57,65.081 h1.27 r315
  text "PA1" at 8.57,64.781 h1.27 r315
  text "PH1" at 1.57,62.581 h1.27 r315
  text "PB3" at 62.67,62.481 h1.27 r315
  text "AGND" at 69.37,62.381 h1.27 r315
  text "PA4" at 8.57,62.281 h1.27 r315
  text "NC" at 68.87,60.381 h1.27 r315
  text "PB0" at 8.57,60.281 h1.27 r315
  text "PA10" at 62.67,59.781 h1.27 r315
  text "VBAT" at 2.07,59.581 h1.27 r315
  text "PF5" at 69.17,57.581 h1.27 r315
  text "PC2" at 1.67,57.481 h1.27 r315
  text "PA2" at 62.57,57.481 h1.27 r315
  text "PC1" at 8.57,57.381 h1.27 r315
  text "PC3" at 1.57,55.081 h1.27 r315
  text "PA3" at 62.57,54.881 h1.27 r315
  text "PC0" at 8.57,54.781 h1.27 r315
  text "PF4" at 69.17,54.781 h1.27 r315
  text "GND" at 62.73,52.581 h1.27 r315
  text "PD4" at 1.67,52.481 h1.27 r315
  text "PE8" at 69.17,52.481 h1.27 r315
  text "PD3" at 8.57,52.281 h1.27 r315
  text "PD5" at 1.67,49.981 h1.27 r315
  text "PF10" at 69.27,49.981 h1.27 r315
  text "PG2" at 8.57,49.781 h1.27 r315
  text "PD13" at 62.67,49.681 h1.27 r315
  text "PD6" at 1.67,47.481 h1.27 r315
  text "PE7" at 69.07,47.381 h1.27 r315
  text "PG3" at 8.57,47.281 h1.27 r315
  text "PD12" at 62.67,47.181 h1.27 r315
  text "PD7" at 1.57,44.981 h1.27 r315
  text "PD14" at 69.27,44.881 h1.27 r315
  text "PE2" at 8.57,44.781 h1.27 r315
  text "PD11" at 62.57,44.581 h1.27 r315
  text "PE3" at 1.67,42.381 h1.27 r315
  text "PD15" at 69.17,42.381 h1.27 r315
  text "PE4" at 8.57,42.281 h1.27 r315
  text "PE10" at 62.67,41.881 h1.27 r315
  text "GND" at 1.77,39.881 h1.27 r315
  text "PF14" at 69.17,39.881 h1.27 r315
  text "PE5" at 8.67,39.381 h1.27 r315
  text "PE12" at 62.67,39.381 h1.27 r315
  text "PF1" at 1.57,37.381 h1.27 r315
  text "PE9" at 69.07,37.381 h1.27 r315
  text "PF2" at 8.57,36.881 h1.27 r315
  text "PE14" at 62.77,36.681 h1.27 r315
  text "GND" at 69.27,34.981 h1.27 r315
  text "PF0" at 1.67,34.881 h1.27 r315
  text "PF8" at 8.47,34.481 h1.27 r315
  text "PE15" at 62.67,34.381 h1.27 r315
  text "PE11" at 69.27,32.281 h1.27 r315
  text "PD1" at 1.67,32.181 h1.27 r315
  text "PF9" at 8.27,32.081 h1.27 r315
  text "PE13" at 62.77,31.781 h1.27 r315
  text "PD0" at 1.67,29.781 h1.27 r315
  text "PF3" at 69.07,29.681 h1.27 r315
  text "PG1" at 8.37,29.581 h1.27 r315
  text "PF13" at 62.67,29.481 h1.27 r315
  text "PG0" at 1.67,27.181 h1.27 r315
  text "PF15" at 69.17,27.181 h1.27 r315
  text "PF12" at 62.57,26.981 h1.27 r315
  text "GND" at 8.27,26.881 h1.27 r315
  text "PE1" at 1.67,24.681 h1.27 r315
  text "PF11" at 69.27,24.581 h1.27 r315
  text "PE6" at 8.37,24.381 h1.27 r315
  text "PG14" at 62.67,23.981 h1.27 r315
  text "PG9" at 1.67,22.081 h1.27 r315
  text "PE0" at 69.27,21.681 h1.27 r315
  text "PG15" at 8.47,21.581 h1.27 r315
  text "GND" at 62.67,21.581 h1.27 r315
  text "PG12" at 2.07,19.181 h1.27 r315
  text "PG10" at 8.47,19.181 h1.27 r315
  text "PD10" at 62.67,18.981 h1.27 r315
  text "PG8" at 69.17,18.981 h1.27 r315
  text "NC" at 1.67,17.081 h1.27 r315
  text "PG13" at 8.27,16.781 h1.27 r315
  text "PG7" at 62.57,16.781 h1.27 r315
  text "PG5" at 69.27,16.681 h1.27 r315
  text "NC" at 7.77,14.781 h1.27 r315
  text "PD9" at 1.67,14.581 h1.27 r315
  text "PG4" at 62.57,14.181 h1.27 r315
  text "PG6" at 69.27,13.981 h1.27 r315
  text "GND" at 61.825,11.55 h1.27 r315
  text "GND" at 8.85,11.5 h1.27 r315
  text "GND" at 69.55,11.425 h1.27 r315
  text "GND" at 1.625,11.1 h1.27 r315
Top Solder:
  rectangle: 51.136,0.91 59.636,2.91
Bottom Solder:
  rectangle: 51.136,0.91 59.636,2.91
M1-Board Shape:
  lines w0.127: 0,2.001 0,131.341 cw(c2,131.341) 2,133.341 68,133.341 cw(c68,131.341) 70,131.341 70,131.341 70,2.001 ; 0.004,2.002 ccw(c2.004,2.002) 2.004,0.002 ; 2,0.001 68,0.001 ; 68,0.006 ccw(c68,2.006) 70,2.006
